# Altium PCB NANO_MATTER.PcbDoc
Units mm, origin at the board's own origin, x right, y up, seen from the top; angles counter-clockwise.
Board outline 43.18 x 17.78 mm, 4 copper layers (TOP, GND, SIG, BOTTOM), stack 1.586 mm thick; 66 components, 64 nets, 297 pads, 160 vias.
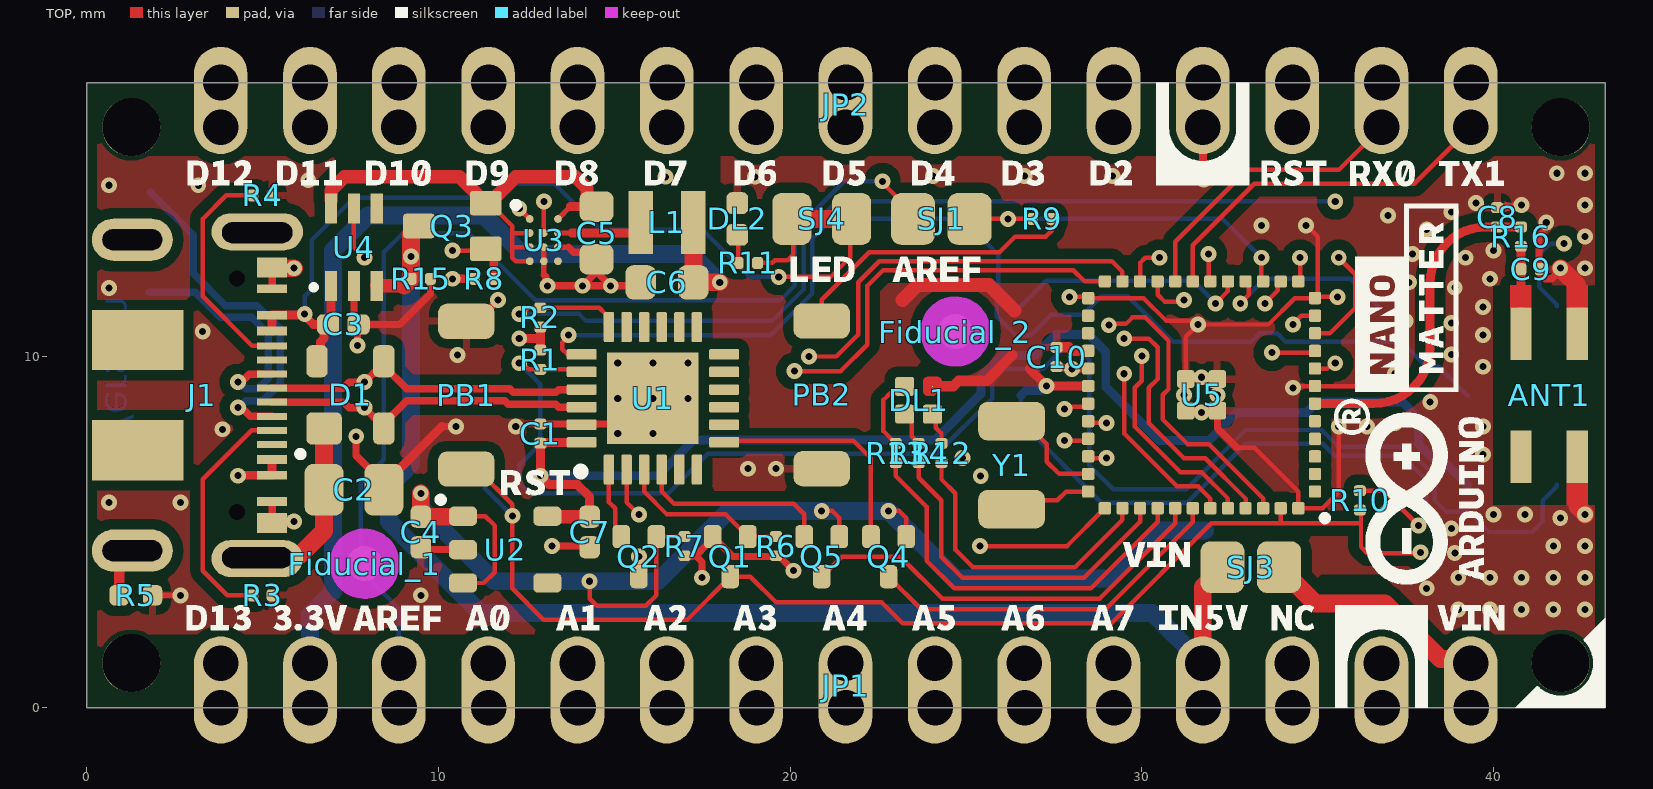
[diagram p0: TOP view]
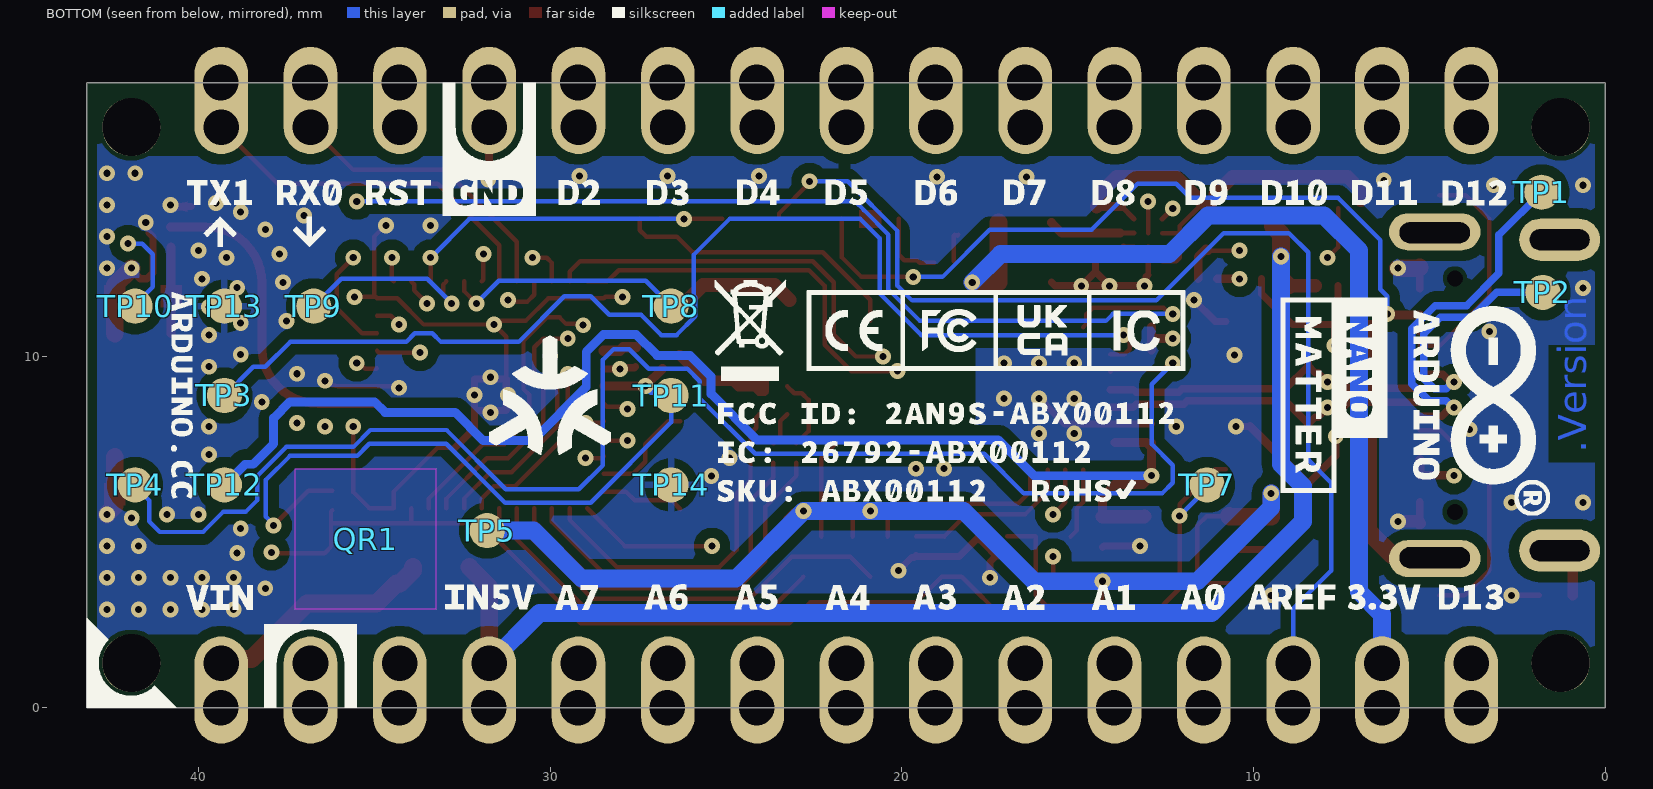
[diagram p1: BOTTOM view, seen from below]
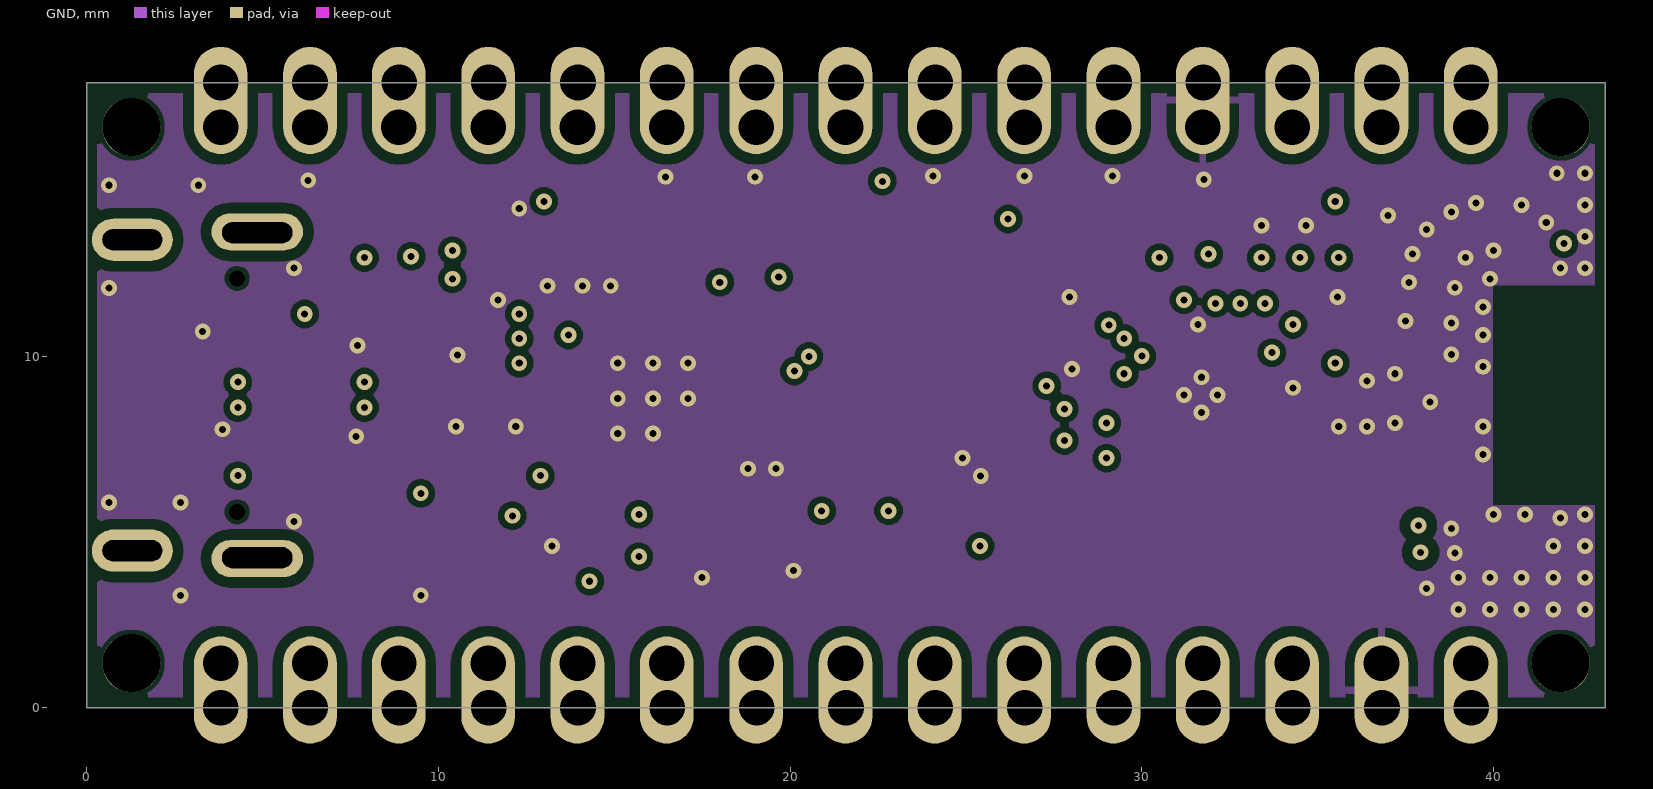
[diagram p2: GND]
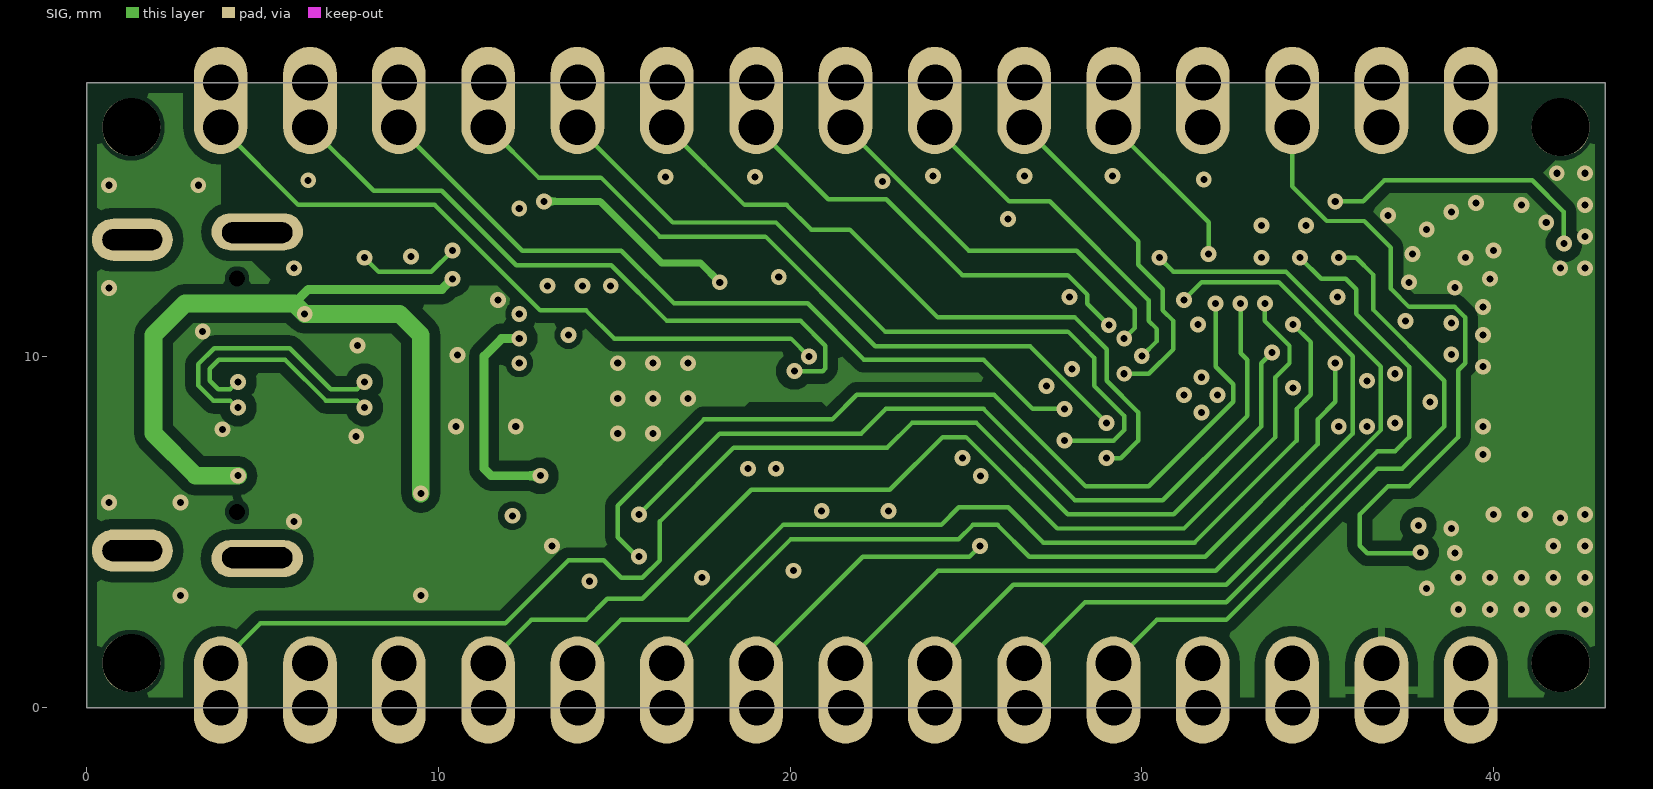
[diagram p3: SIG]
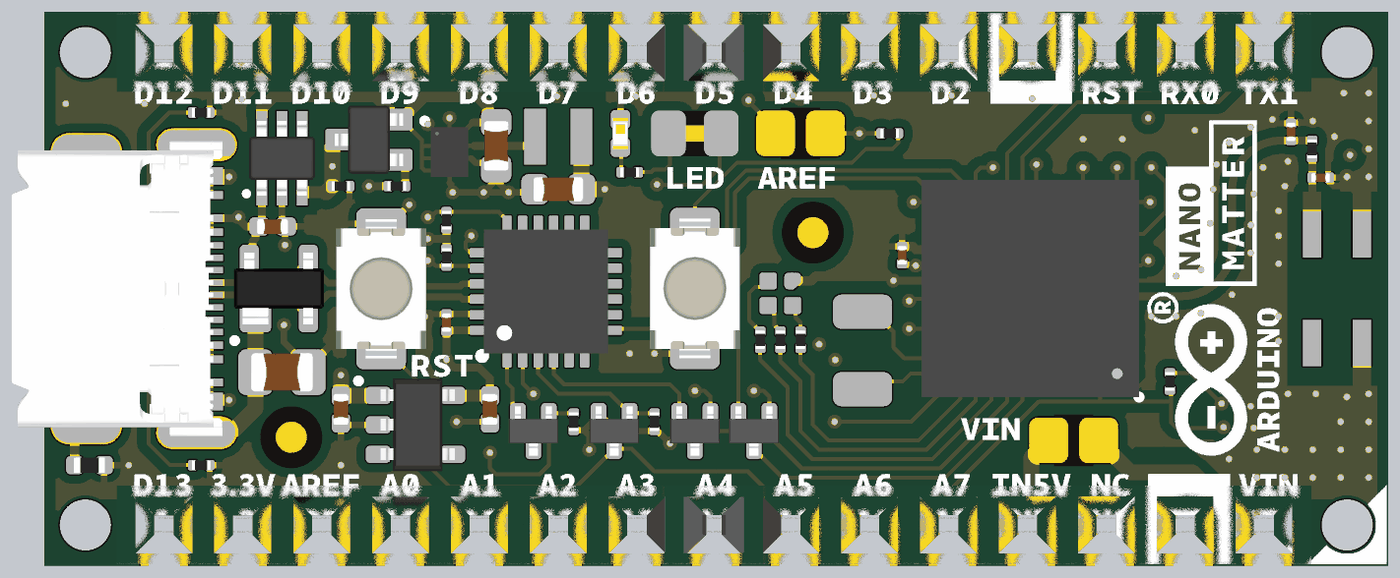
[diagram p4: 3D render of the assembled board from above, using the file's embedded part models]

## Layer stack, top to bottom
Top Solder: solder mask 0.0102, Solder Resist, Dk 3.5
TOP: signal copper 0.018
Dielectric 1: prepreg 0.14, PP-014, Dk 4.2
GND: signal copper 0.035
Dielectric2: core 1.2, FR-4, Dk 4.8
SIG: signal copper 0.035
Dielectric3: prepreg 0.14, PP-014, Dk 4.2
BOTTOM: signal copper 0.018
Bottom Solder: solder mask 0.0102, Solder Resist, Dk 3.5

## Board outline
0,0 0,17.78 43.18,17.78 43.18,0

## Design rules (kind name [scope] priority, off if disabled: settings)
BoardOutlineClearance USBC_outlineclearance [Component = 'J1'] p1: gap=0.1 ignorepadtopadclearanceinfootprint=FALSE
BoardOutlineClearance Castellated [((ObjectKind = 'Pad') And (Component = 'JP1')) OR                                                                                    ((ObjectKind = 'Pad') And (Component = 'JP2'))] p2: gap=0 ignorepadtopadclearanceinfootprint=FALSE
BoardOutlineClearance Silks [(OnLayer('Top Overlay') OR OnLayer('Bottom Overlay'))] p3: gap=0 ignorepadtopadclearanceinfootprint=FALSE
BoardOutlineClearance [All] p4: gap=0.3 ignorepadtopadclearanceinfootprint=FALSE
Clearance SolderJumpers [(ObjectKind = 'Region') And (Net = 'NetR11_2') And (Area = '0.315 sq.') vs (ObjectKind = 'Pad') And (Layer = 'TOP') And (Net = 'VUSB') And (Component = 'SJ4') And (Name = 'SJ4-1')] p1: gap=0 ignorepadtopadclearanceinfootprint=TRUE
Clearance Clearance_Teardrop [IsTeardrop] p2: gap=0.127 ignorepadtopadclearanceinfootprint=TRUE
Clearance COPPER_0.3mm [All] p3: gap=0.127 ignorepadtopadclearanceinfootprint=TRUE except(0.3: Arc-Fill Arc-Poly Arc-Region Track-Fill Track-Poly Track-Region SMDPad-Fill SMDPad-Poly SMDPad-Region THPad-Fill THPad-Poly THPad-Region Via-Fill Via-Poly Via-Region Fill-Fill Fill-Poly Fill-Region Poly-Poly Poly-Region Region-Region)
Clearance "Generic clearance 0.127mm" [All] p4: gap=0.127 ignorepadtopadclearanceinfootprint=TRUE
ComponentClearance [All] p1: gap=0.2 collisioncheckmode=3 verticalgap=0 showdistances=TRUE
DiffPairsRouting USB [InDifferentialPairClass('USB')] p1: maxlimit=0.254 minlimit=0.127 mostfreqgap=0.254 toplayer_maxgap=0.127 toplayer_prefgap=0.127 toplayer_minwidth=0.213 toplayer_maxwidth=0.213 toplayer_prefwidth=0.213 midlayer2_mingap=0.197 midlayer2_maxgap=0.197 midlayer2_prefgap=0.197 midlayer2_minwidth=0.127 midlayer2_maxwidth=0.127 midlayer2_prefwidth=0.127 bottomlayer_maxgap=0.127 bottomlayer_prefgap=0.127 bottomlayer_minwidth=0.213 bottomlayer_maxwidth=0.213 bottomlayer_prefwidth=0.213 impedanceprofiledriven=TRUE impedanceprofileid={E6B00C31-4C8E-439C-824F-D2B2CDC26F9C} impedanceprofilevalue=90.000000 maxuncoupledlength=12.7
Height [All] p1: minheight=0 maxheight=30 prefheight=12.7
HoleSize [All] p1: absolutevalues=TRUE maxlimit=30 minlimit=0.2 maxpercent=80.000 minpercent=20.000
HoleToHoleClearance [All] p1: gap=0.25 allowstackedmicrovias=FALSE
PlaneConnect [All] p1: pad.planeconnectstyle=Relief pad.reliefexpansion=0.508 pad.reliefentries=4 pad.reliefconductorwidth=0.254 pad.reliefairgap=0.254 via.planeconnectstyle=Direct via.reliefexpansion=0.508 via.reliefentries=4 via.reliefconductorwidth=0.254 via.reliefairgap=0.254
PolygonConnect [All] p1: thpad.connectstyle=Relief thpad.reliefconductorwidth=0.2 thpad.reliefentries=4 thpad.polygonreliefangle="90 Angle" thpad.airgapwidth=0.254 smdpad.connectstyle=Relief smdpad.reliefconductorwidth=0.2 smdpad.reliefentries=4 smdpad.polygonreliefangle="90 Angle" smdpad.airgapwidth=0.254 via.connectstyle=Direct via.reliefconductorwidth=0.254 via.reliefentries=4 via.polygonreliefangle="90 Angle" via.airgapwidth=0.254
RoomDefinition TOP [InComponentClass('TOP')] p1: confinementstyle=ConfineIn formatcopy=TRUE lockcomponents=FALSE outline 44.4,1.5 48.8,1.5 48.8,8.5 44.4,8.5
RoutingVias StandardVias [All] p1: holewidth=0.2 width=0.45 viastyle="Through Hole" minholewidth=0.2 minwidth=0.45 maxholewidth=0.2 maxwidth=0.45
SMDToCorner [All] p1: distance=39370
ShortCircuit short_jumper [(ObjectKind = 'Region') And (Net = 'NetR11_2') And (Area = '0.315 sq.') vs (ObjectKind = 'Pad') And (Layer = 'TOP') And (Net = 'VUSB') And (Component = 'SJ4') And (Name = 'SJ4-1')] p1: allowed=TRUE
ShortCircuit [All] p2: allowed=FALSE
SilkToSilkClearance [All] p1: silktosilkclearance=0.2
SilkToSolderMaskClearance [IsPad] p1: minsilkscreentomaskgap=0.1 clearancetoexposedcopper=TRUE
SolderMaskExpansion VIAtented [IsVia] p1: expansion=0.102 istentingtop=TRUE
SolderMaskExpansion [All] p2: expansion=0.05 istentingtop=FALSE
UnConnectedPin [All] p1:
UnRoutedNet [All] p1: checkbadconnections=TRUE
ViasUnderSMD [All] p1: allowed=FALSE
Width [All] p1: maxlimit=0.508 minlimit=0.127 preferedwidth=0.254
Width StandardTraces [InNetClass('ANT')] p2: maxlimit=5 minlimit=0.127 preferedwidth=0.239 toplayer_minwidth=0.239 toplayer_maxwidth=0.239 bottomlayer_minwidth=0.239 bottomlayer_maxwidth=0.239 impedanceprofiledriven=TRUE impedanceprofileid={62AF9E0A-4658-4788-9E1D-AE6CB9A6C4CD} impedanceprofilevalue=50.000000 minimp=50.000000 maximp=50.000000 favimp=50.000000
20 further rules are at their usual default settings.

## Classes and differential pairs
component class TOP: Fiducial_1 Fiducial_2 QR1
net class ANT: NetANT1_1 NetC8_1
component class U_MGM240S: ANT1 C8 C9 C10 R16 TP7 TP8 TP9 TP14 U5 Y1
differential pair class USB: D
component class U_USB: C2 D1 J1 R3 R4 R5 TP1 TP2
component class "U_SAMD11 USB Bridge": C1 Q1 Q2 Q4 Q5 R1 R2 R6 R7 TP3 TP4 TP10 TP13 U1
component class U_POWER: C3 C4 C5 C6 C7 L1 L? Q3 R8 R15 TP5 TP11 TP12 U2 U3 U4
component class U_INTERFACE: DL1 DL2 JP1 JP2 PB1 PB2 R9 R10 R11 R12 R13 R14 SJ1 SJ3 SJ4
differential pair D: +D_P -D_N

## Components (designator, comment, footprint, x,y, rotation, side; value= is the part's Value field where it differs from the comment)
ANT1 "2450AT42E010BE" 2450AT42E0100E 41.58,8.89 r270 top
C1 "CL03A104KP3NNNC" CAP-0201 12.9,7.8 r270 top value=100nF
C2 "FV21X472K102ECG" CAP-0805 7.6,6.2 r180 top value=4.7nF
C3 "CL05A105KP5NNNC" CAP-0402 7.3,10.9 r0 top value=1µF
C4 "CL05A105KP5NNNC" CAP-0402 9.5,5 r90 top value=1µF
C5 "C1608A106M250NT" CAP-0603 14.5,13.5 r270 top value=10µF
C6 "C1608A106M250NT" CAP-0603 16.5,12.1 r0 top value=10µF
C7 "CL05A105KP5NNNC" CAP-0402 14.3,5 r90 top value=1µF
C8 "CAP-0201-DNP" CAP-0201 40.1,13.95 r90 top
C9 "CAP-0201-DNP" CAP-0201 41.055,12.473 r0 top
C10 "CL03A104KP3NNNC" CAP-0201 27.575,9.975 r90 top value=100nF
D1 "PRTR5V0U2X,215" SOT190P230X110-4N 7.5,8.9 r0 top
DL1 "UHD1110-FKA-CL1A13R3Q1BBQFMF3" UHD1110-FKA-CL1A13R3Q1BBQFMF3 23.655,8.745 r270 top
DL2 "KPHHS-1005SURCK" 0402-LED 18.5,13.9 r90 top
Fiducial_1 "Fiducial mark 1mm" "Fiducial mark 1mm-Footprint-1" 7.9,4.1 r90 top
Fiducial_2 "Fiducial mark 1mm" "Fiducial mark 1mm-Footprint-1" 24.7,10.7 r90 top
J1 "CX90B-16P" CX90B-16P-Footprint-1 3.288,8.89 r270 top locked
JP1 "PINHD-1X15-NANO-ANALOG-CASTELLATED" PINHD-1X14_5VF#1 3.81,1.27 r180 top locked
JP2 "PINHD-1X15-NANO-DIGITAL-CASTELLATED" PINHD-1X14_5VF#2 39.37,16.51 r0 top locked
L1 "MAKK2016T3R3M" MAKK2016T3R3M-Footprint-1 16.5,13.8 r0 top value=3.3µH
PB1 "IT-1185AP1C-160G-GTR" C&K_PTS820_NO_HOLES-1 10.794,8.89 r270 top locked
PB2 "IT-1185AP1C-160G-GTR" C&K_PTS820_NO_HOLES-1 20.9,8.9 r90 top
Q1 "2N7002T-7-F" SOT523 18.3,4.3 r180 top
Q2 "2N7002T-7-F" SOT523 15.7,4.3 r180 top
Q3 "DMP2165UW-7" DIOD-SOT323-3_V 10.4,13.7 r180 top
Q4 "2N7002T-7-F" SOT523 22.8,4.3 r180 top
Q5 "2N7002T-7-F" SOT523 20.9,4.3 r180 top
QR1 "QR CODE 4x4mm" "QR CODE 4x4mm" 35.25,4.8 r180 bottom
R1 "RC0201FR-07100KL" RES-0201 12.9,9.9 r90 top value=100k
R2 "RC0201FR-07100KL" RES-0201 12.9,11.1 r90 top value=100k
R3 "RC0201FR-075K1L" RES-0201 5,3.2 r180 top value=5.1k
R4 "RC0201FR-075K1L" RES-0201 5,14.573 r180 top value=5.1k
R5 "CRCW04021M00FKED" RES-0402 1.4,3.2 r180 top value=1M
R6 "RC0201FR-07100KL" RES-0201 19.6,4.6 r270 top value=100k
R7 "RC0201FR-07100KL" RES-0201 17,4.6 r270 top value=100k
R8 "RC0201FR-07100KL" RES-0201 11.3,12.2 r0 top value=100k
R9 "RC0201FR-071KL" RES-0201 27.175,13.9 r180 top value=1k
R10 "RC0201FR-075K1L" RES-0201 36.2,5.9 r90 top value=5.1k
R11 "RC0201FR-071KL" RES-0201 18.8,12.65 r0 top value=1k
R12 "CRCW0201499RFKED" RES-0201 24.305,7.245 r270 top value=499
R13 "CRCW0201499RFKED" RES-0201 23.005,7.245 r270 top value=499
R14 "CRCW0201499RFKED" RES-0201 23.655,7.245 r270 top value=499
R15 "RC0201FR-0710ML" RES-0201 9.5,12.2 r0 top value=10M
R16 "CRCW02010000Z0ED" RES-0201 40.78,13.4 r270 top value=0
SJ1 "SMD solder JUMPER 0805" SJ#1 24.3,13.9 r0 top
SJ3 "SMD solder JUMPER 0805" SJ#1 33.1,4 r180 top
SJ4 "SMD solder JUMPER CLOSED" SJ#2 20.9,13.9 r180 top
TP1 "Test point 1.00mm" TP-1.00MM 1.81,14.66 r90 bottom
TP2 "Test point 1.00mm" TP-1.00MM 1.778,11.811 r90 bottom
TP3 "Test point 1.00mm" TP-1.00MM 39.263,8.881 r90 bottom locked
TP4 "Test point 1.00mm" TP-1.00MM 41.803,6.341 r90 bottom locked
TP5 "Test point 1.00mm" TP-1.00MM 31.795,5.041 r90 bottom locked
TP7 "Test point 1.00mm" TP-1.00MM 11.323,6.341 r90 bottom
TP8 "Test point 1.00mm" TP-1.00MM 26.563,11.421 r90 bottom
TP9 "Test point 1.00mm" TP-1.00MM 36.723,11.421 r90 bottom
TP10 "Test point 1.00mm" TP-1.00MM 41.803,11.421 r90 bottom locked
TP11 "Test point 1.00mm" TP-1.00MM 26.563,8.881 r90 bottom
TP12 "Test point 1.00mm" TP-1.00MM 39.263,6.341 r90 bottom locked
TP13 "Test point 1.00mm" TP-1.00MM 39.263,11.421 r90 bottom locked
TP14 "Test point 1.00mm" TP-1.00MM 26.563,6.341 r90 bottom
U1 "ATSAM-D11-D14A-MUT" VQFN24 16.1,8.8 r180 top
U2 "AP2112K-3.3TRG1" SOT25 11.9,4.5 r270 top
U3 "MP28210GC–Z" MP28210 13,13.3 r270 top
U4 "LM66100DCKR" SOT65P210X110-6N 7.6,13.1 r90 top
U5 "MGM240SD22VNA2R" MGM240SD22VNA 31.7,8.9 r180 top locked
Y1 "CM315D32768DZFT" ABS07 26.3,6.9 r90 top

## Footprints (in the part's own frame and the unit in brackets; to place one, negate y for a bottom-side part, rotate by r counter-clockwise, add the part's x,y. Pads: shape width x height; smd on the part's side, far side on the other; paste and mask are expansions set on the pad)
0402-LED [mm]
  rrect50% 0.62x0.62 smd mask+0.05: A(-0.45,0) C(0.45,0)
  body extent -0.5,-0.25 0.5,0.25, height 0.5
2450AT42E0100E [mm]
  rect 1.5x0.6 smd: 1(-1.75,-0.8) 2(1.75,-0.8) 3(1.75,0.8) 4(-1.75,0.8)
  TOP region: -2.5,0.5 -3.13,0.5 -3.13,1.1 -2.5,1.1
  TOP region: -2.5,-1.1 -3.13,-1.1 -3.13,-0.5 -2.5,-0.5
  TOP region: 2.5,0.5 3.13,0.5 3.13,1.1 2.5,1.1
  body extent -2.5,-1 2.5,1, height 1.7
ABS07 [mm]
  rrect50% 1.1x1.9 smd: 1(-1.25,0) 2(1.25,0)
  body extent -1.65,-0.83 1.65,0.83, height 0.9
C&K_PTS820_NO_HOLES-1 [mm]
  rrect49% 1x1.6 smd mask+0.05: 1(-2.1,0) 2(2.1,0)
  body extent -2.25,-1.45 2.25,1.45, height 2
CAP-0201 [mm] "Chip Capacitor, 2-Leads, Body 0201 (in) 0603 (mm) IPC Medium Density"
  rrect52% 0.31x0.34 smd mask+0.05: 1(-0.275,0) 2(0.275,0)
  body extent -0.3,-0.15 0.3,0.15, height 0.3
CAP-0402 [mm] "Chip Capacitor, 2-Leads, Body  0402 (in) 1005 (mm), IPC Medium Density"
  rrect52% 0.63x0.58 smd mask+0.05: 1(-0.435,0) 2(0.435,0)
  body extent -0.5,-0.25 0.5,0.25, height 0.5
CAP-0603 [mm] "Chip Capacitor, Body 0603 imperial,1.6x0.8mm, IPC High Density"
  rrect51% 0.87x0.97 smd mask+0.05: 1(-0.75,0) 2(0.75,0)
  body extent -0.8,-0.4 0.8,0.4, height 0.8
CAP-0805 [mm] "Chip Capacitor, Body 0805 imperial, 2.0x1.2mm, IPC Medium Density"
  rrect45% 1.11x1.47 smd mask+0.05: 1(-0.85,0) 2(0.85,0)
  body extent -1,-0.62 1,0.63, height 1.25
CX90B-16P-Footprint-1 [mm]
  rect 0.57x0.85 smd mask+0.05: A1(-3.635,1.988) A12(3.635,1.988)
  rect 0.25x0.85 smd mask+0.05: A4(-2.275,1.988) A9(2.275,1.988) B1(3.025,1.988) B4(1.825,1.988) B9(-1.825,1.988) B12(-3.025,1.988)
  rect 0.2x0.85 smd mask+0.05: A5(-1.4,1.988) A6(-0.6,1.988) A7(0.6,1.988) A8(1.4,1.988) B5(1,1.988) B6(0.2,1.988) B7(-0.2,1.988) B8(-1,1.988)
  round 0.2 hole 0.45 unplated paste-2539.97 mask+0.2: FIXING(-3.32,0.988) FIXING(3.32,0.988)
  rect 1.71x2.6 smd paste-0.3 mask+0.05: FIXING(-1.565,-1.837) FIXING(1.565,-1.837)
  oval 1.05x2.6 hole 0.6 slot 2 at 90 deg copper offset -0.025,0 mask+0.05: SHIELD1(-4.62,1.563)
  oval 1.05x2.6 hole 0.6 slot 2 at 90 deg copper offset 0.025,0 mask+0.05: SHIELD2(4.62,1.563)
  oval 1.2x2.3 hole 0.6 slot 1.7 at 90 deg mask+0.05: SHIELD3(-4.42,-1.987) SHIELD4(4.42,-1.987)
  body extent -4.77,-4.4 4.77,2.4, height 3.17
DIOD-SOT323-3_V [mm] "SOT323, 3-Leads, Body 2.2x1.35mm, Pitch 0.65mm"
  rrect25% 0.9x0.7 smd mask+0.05: 1(-0.95,0.65) 2(-0.95,-0.65) 3(0.95,0)
  body extent -1.1,-1.1 1.1,1.1, height 1.07
"Fiducial mark 1mm-Footprint-1" [mm]
  round 1 smd paste-10 mask+0.5: 1(0,0)
  TOP keep-out circle w1: c0,0 r0.5
MAKK2016T3R3M-Footprint-1 [mm]
  rect 0.7x1.8 smd mask+0.05: 1(-0.75,0) 2(0.75,0)
  body extent -1,-0.8 1,0.8, height 1
MGM240SD22VNA [mm]
  rrect30% 0.35x0.35 smd mask+0.05: 1(-3.225,2.75) 2(-3.225,2.25) 3(-3.225,1.75) 4(-3.225,1.25) 5(-3.225,0.75) 6(-3.225,0.25) 7(-3.225,-0.25) 8(-3.225,-0.75) 9(-3.225,-1.25) 10(-3.225,-1.75) 11(-3.225,-2.25) 12(-3.225,-2.75) 13(-2.75,-3.225) 14(-2.25,-3.225) 15(-1.75,-3.225) 16(-1.25,-3.225) 17(-0.75,-3.225) 18(-0.25,-3.225) 19(0.25,-3.225) 20(0.75,-3.225) 21(1.25,-3.225) 22(1.75,-3.225) 23(2.25,-3.225) 24(2.75,-3.225) 25(3.225,-2.75) 26(3.225,-2.25) 27(3.225,-1.75) 28(3.225,-1.25) 29(3.225,-0.75) 30(3.225,-0.25) 31(3.225,0.25) 32(3.225,0.75) 33(3.225,1.25) 34(3.225,1.75) 35(3.225,2.25) 36(3.225,2.75) 37(2.75,3.225) 38(2.25,3.225) 39(1.75,3.225) 40(1.25,3.225) 41(0.75,3.225) 42(0.25,3.225) 43(-0.25,3.225) 44(-0.75,3.225) 45(-1.25,3.225) 46(-1.75,3.225) 47(-2.25,3.225) 48(-2.75,3.225)
  rrect30% 0.5x0.5 smd mask+0.05: 49(-0.45,0.45) 50(0.45,0.45) 51(0.45,-0.45) 52(-0.45,-0.45)
  silkscreen extent -3.55,3.46 -3.46,3.55, body extent -3.5,-3.5 3.5,3.5, height 1.27
MP28210 [mm]
  round 0.22 smd paste+0 mask+0.05: A1(-0.6,-0.4) A3(-0.6,0.4) B1(-0.2,-0.4) B2(-0.2,0) B3(-0.2,0.4) C1(0.2,-0.4) C2(0.2,0) C3(0.2,0.4) D1(0.6,-0.4) D2(0.6,0) D3(0.6,0.4)
  silkscreen extent -1.05,-0.85 -0.95,-0.75, body extent -0.8,-0.6 0.8,0.6, height 0.58
PINHD-1X14_5VF#1 [mil]
  oval 60x120 hole 40 copper offset 0,30 paste-99999: 1(0,0) 2(-100,0) 3(-199.41,0) 4(-299.41,0) 5(-399.41,0) 6(-499.41,0) 7(-599.41,0) 8(-699.41,0) 9(-799.41,0) 10(-899.41,0) 11(-999.41,0) 12(-1099.41,0) 13(-1199.41,0) 14(-1299.41,0) 15(-1399.41,0)
  round 27.56 hole 40 mask+7.87: 1(0,50) 2(-100,50) 3(-200,50) 4(-300,50) 5(-400,50) 6(-500,50) 7(-600,50) 8(-700,50) 9(-800,50) 10(-900,50) 11(-1000,50) 12(-1100,50) 13(-1200,50) 14(-1300,50) 15(-1400,50)
  body extent -1454,-50 60,50, height 335
PINHD-1X14_5VF#2 [mil]
  oval 60x120 hole 40 copper offset 0,30 paste-99999: 1(-0.59,0) 2(-100.59,0) 3(-200.59,0) 4(-300.59,0) 5(-400.59,0) 6(-500.59,0) 7(-600.59,0) 8(-700.59,0) 9(-800.59,0) 10(-900.59,0) 11(-1000.59,0) 12(-1100.59,0) 13(-1200.59,0) 14(-1300,0) 15(-1400,0)
  round 27.56 hole 40 mask+7.87: 1(0,50) 2(-100,50) 3(-200,50) 4(-300,50) 5(-400,50) 6(-500,50) 7(-600,50) 8(-700,50) 9(-800,50) 10(-900,50) 11(-1000,50) 12(-1100,50) 13(-1200,50) 14(-1300,50) 15(-1400,50)
  body extent -1460,-50 54,50, height 335
"QR CODE 4x4mm" [mm]
  TOP keep-out region: -2,2 2,2 2,-2 -2,-2
RES-0201 [mm] "Chip Resistor, 2-Leads, Body 0201 (in) 0603 (mm) IPC Medium Density"
  rrect52% 0.31x0.34 smd mask+0.05: 1(-0.275,0) 2(0.275,0)
  body extent -0.3,-0.15 0.3,0.15, height 0.24
RES-0402 [mm] "Chip Resistor, 2-Leads, Body  0402 (in) 1005 (mm), IPC Medium Density"
  rrect51% 0.55x0.58 smd mask+0.05: 1(-0.475,0) 2(0.475,0)
  body extent -0.5,-0.25 0.5,0.25, height 0.34
SJ#1 [mm]
  rrect45% 1.25x1.47 smd paste-0.635: 1(-0.805,0) 2(0.805,0)
SJ#2 [mm]
  rrect45% 1.11x1.47 smd mask+0: 1(-0.85,0) 2(0.85,0)
  TOP region: -0.31,0.254 -0.31,-0.254 0.31,-0.254 0.31,0.254
SOT25 [mil]
  rrect50% 21.65x31.5 smd mask+1.97: 1(-37.4,-47.24) 2(0,-47.24) 3(37.4,-47.24) 4(37.4,47.24) 5(-37.4,47.24)
  silkscreen extent -58,-74 -54,-70, body extent -59,-44 59,50, height 43
SOT65P210X110-6N [mm] "SOT23, 6-Leads, Body 1,99x2,10mm, Pitch 0,65mm, IPC Medium Density"
  rect 0.85x0.35 smd mask+0.05: 1(-1.1,0.65) 2(-1.1,0) 3(-1.1,-0.65) 4(1.1,-0.65) 5(1.1,0) 6(1.1,0.65)
  silkscreen extent -1.19,1.09 -1.09,1.19, body extent -1.2,-1.06 1.2,1.06, height 1.12
SOT190P230X110-4N [mm]
  rrect33% 1.01x0.91 smd paste+0 mask+0.05: 1(-0.75,-0.955)
  rrect49% 0.61x0.91 smd paste+0 mask+0.05: 2(0.95,-0.955) 3(0.95,0.955) 4(-0.95,0.955)
  silkscreen extent -1.47,-1.73 -1.37,-1.63, body extent -1.45,-1.15 1.45,1.15, height 1
SOT523 [mm]
  rrect50% 0.5x0.66 smd: D(0,0.57) G(-0.5,-0.57) S(0.5,-0.57)
  body extent -0.8,-0.8 0.8,0.8, height 0.8
TP-1.00MM [mm]
  rrect100% 1x1 smd paste-2.54: X(0,0)
UHD1110-FKA-CL1A13R3Q1BBQFMF3 [mm]
  rrect25% 0.54x0.54 smd mask+0.05: 1(-0.395,-0.395) 2(0.395,-0.395) 3(0.395,0.395)
  round 0.025 smd mask+0.05: 4(-0.395,0.395)
  TOP region: -0.35,0.665 -0.125,0.44 -0.125,0.265 -0.136,0.212 -0.166,0.166 -0.212,0.136 -0.265,0.125 -0.265,0.125 -0.525,0.125 -0.578,0.136 -0.624,0.166 -0.654,0.212 -0.665,0.265 -0.665,0.265 -0.665,0.525 -0.654,0.578 -0.624,0.624 -0.578,0.654 -0.525,0.665 -0.525,0.665
  body extent -0.5,-0.5 0.5,0.5, height 0.63
VQFN24 [mm]
  rrect25% 0.3x0.85 smd mask+0.05: 1(1.25,2.025) 2(0.75,2.025) 3(0.25,2.025) 4(-0.25,2.025) 5(-0.75,2.025) 6(-1.25,2.025) 13(-1.25,-2.025) 14(-0.75,-2.025) 15(-0.25,-2.025) 16(0.25,-2.025) 17(0.75,-2.025) 18(1.25,-2.025)
  rrect25% 0.85x0.3 smd mask+0.05: 7(-2.025,1.25) 8(-2.025,0.75) 9(-2.025,0.25) 10(-2.025,-0.25) 11(-2.025,-0.75) 12(-2.025,-1.25) 19(2.025,-1.25) 20(2.025,-0.75) 21(2.025,-0.25) 22(2.025,0.25) 23(2.025,0.75) 24(2.025,1.25)
  rect 2.6x2.6 smd paste-5 mask+0.05: EXP(0,0)
  silkscreen extent 1.95,1.98 2.15,2.18, body extent -2,-2 2,2, height 0.9

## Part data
ANT1: library part Y0004-A.2, "ANTENNA CHIP 2.4GHZ", Frequency=2.4GHz, Manufacturer=Johanson, Max Frequency=2.48GHz, Max Power Dissipation=2W
C1 C10: library part C0113-A.6, "CAP CHIP 0201 100nF 10% 10V X5R", Case Code (Imperial)=0201, Dielectric=X5R, Manufacturer="Samsung Electro-Mechanics", Tolerance=10%, Voltage=10V
C2: library part C0059-A.14, "CAP CHIP 0805 4.7nF 10% 1000V X7R", Case Code (Imperial)=0805, Dielectric=X7R, Manufacturer="PSA Shenzen", Manufacturer 2=KEMET, Part number 2=C0805V472KDRACTU, Part number 3=C0805C472KDRACTU, Tolerance=10%, Voltage=1kV
C3 C4 C7: library part C0017-A.14, "CAP CHIP 0402 1uF 10% 10V X5R", Case Code (Imperial)=0402, Dielectric=X5R, Manufacturer="Samsung Electro-Mechanics", Manufacturer 2="Murata Electronics", Part number 2=GCM155C71A105KE38D, Tolerance=10%, Voltage=10V
C5 C6: library part C0047-A.18, "CAP CHIP 0603 10uF 20% 25V X5R", Case Code (Imperial)=0603, Dielectric=X5R, Manufacturer=Hottech, Manufacturer 2="Murata Electronics", Part number 2=CL10A106MA8NRNC, Tolerance=20%, Voltage=25V
C8 C9: library part UT0015-A.7, "DNP CAP CHIP 0201"
D1: library part D0025-A.5, "TVS ARRAY 4LIN.8kV 1pF SOT143B", Manufacturer=Nexperia
DL1: library part L0026-A.4, "LED RGB BLACK BODY SMD", Manufacturer="Cree LED"
DL2: library part L0004-A.7, "LED SMD 0402 RED630 220mcd 120^", Manufacturer=Kingbright
Fiducial_1 Fiducial_2: library part UT0023-A.7, "Fiducial mark 1mm clearance 2mm"
J1: library part J0272-A.3, "CONN RCPT USB3.1 TYPEC 16POS SMD", Manufacturer=Hirose
JP1: library part J0158-A.4, "CONN THD SOCKET F/1/D 15V JANALOG NANO-TYPE CASTELLATED"
JP2: library part J0183-A.4, "CONN THD SOCKET F/1/D 15V JDIGITAL NANO-TYPE CASTELLATED"
L1: library part I0045-A.10, "IND CHIP 0806 3.3 uH 20% 1.2A", Case Code (Imperial)=0806, Case Code (Metric)=2016, Current Rating=1.2A, DC Resistance (DCR)=255mR, Inductance=3.3µH, Manufacturer="Taiyo Yuden", Manufacturer 2=Murata, Manufacturer Part Number 2=LQM2MPN3R3NG0L, Max DC Current=1.15A, Max Operating Temperature=105°C, Min Operating Temperature=-40°C, Package Quantity=3000, Resistor Type=Wirewound, Test Frequency=2MHz, Tolerance=20%
PB1 PB2: library part B0001-A.7, "PUSHBUTTON WHITE NO ANCHORS", Color=White, Manufacturer=Switronic
Q1 Q2 Q4 Q5: library part T0003-A.2, "MOSFET N-CH 60V 115mA SOT523", Manufacturer="Diodes Inc."
Q3: library part T0050-2, "MOSFET P-CH Vds -20V, Id 2A, VGSS+-12V, SOT323", Manufacturer="Diodes Incorporated"
QR1: library part QR-0001-A.2, "QR CODE 4x4mm on layer 34 (This is not a component)", Manufacturer="This is not a component"
R1 R2 R6 R7 R8: library part R0146-A.21, "RES CHIP 0201 100k 1% 1/20W", Case Code (Imperial)=0201, Manufacturer=Yageo, Manufacturer 2="Samsung Electro-Mechanics", Power=50mW, Temperature Coefficient=200ppm, Tolerance=1%
R3 R4 R10: library part R0169-A.24, "RES CHIP 0201 5.1k 1% 1/20W", Case Code (Imperial)=0201, Manufacturer=Yageo, Power=50mW, Temperature Coefficient=200ppm, Tolerance=1%
R5: library part R0058-A.24, "RES CHIP 0402 1M 1% 1/16W", Case Code (Imperial)=0402, Manufacturer=Vishay, Power=62.5mW, Temperature Coefficient=100ppm, Tolerance=1%
R9 R11: library part R0195-A.22, "RES CHIP 0201 1k 1% 1/20W", Case Code (Imperial)=0201, Manufacturer=Yageo, Power=50mW, Temperature Coefficient=200ppm, Tolerance=1%
R12 R13 R14: library part R0185-A.22, "RES CHIP 0201 499R 1% 1/20W", Case Code (Imperial)=0201, Manufacturer=Vishay, Power=50mW, Temperature Coefficient=100ppm, Tolerance=1%
R15: library part R0297-A.1, "RES CHIP 0201 10M 1% 1/20W", Case Code (Imperial)=0201, Manufacturer=YAGEO, Power=50mW, Temperature Coefficient=200ppm, Tolerance=1%
R16: library part R0140-A.21, "RES CHIP 0201 0R", Case Code (Imperial)=0201, Manufacturer=Vishay, Power=50mW, Temperature Coefficient=0ppm, Tolerance=0%
SJ1 SJ3: library part UT0002-A.5, "Solder Jumper 0805 THIS IS NOT A COMPONENT"
SJ4: library part UT0006-A.14, "Solder Jumper shorted pads. This is not a component"
TP1 TP2 TP3 TP4 TP5 TP7 TP8 TP9 TP10 TP11 TP12 TP13 TP14: library part UT0013-A.6, Manufacturer="This is not a component"
U1: library part U0040-A.8, "IC uC Cortex M0, 16KB flash, 4KB SRAM, 48MHz, USB, 3x SERCOM, RTC, 12PWM, ADC 12b, DAC 10b, VDD 1.6V to 3.6V, QFN24 4x4mm", Manufacturer=Microchip
U2: library part U0027-A.11, "IC LDO Vin max 6.5V Vout 3V3 Iout 600mA +EN  SOT25", Manufacturer="Diodes Inc"
U3: library part U0073-A.4, "IC BUCK Vin 2-5.5V, Iout 1A, Fsw 1.5MHz, Duty 100%, Iq 500nA, CSP12 1.2x1.6mm", Manufacturer=MPS
U4: library part U0164-A.5, "IC IDEAL DIODE 5.5V 1.5A WITH INPUT POLARITY PROTECTION", Manufacturer="Texas Instruments"
U5: library part U0354-A.5, "802.15.4, Bluetooth Bluetooth v5.3, Thread, Zigbee® Transceiver Module 2.4GHz PCB Trace, Antenna Not Included, U.FL Surface Mount", Manufacturer="Silicon Labs"
Y1: library part X0003-A.5, "CRYSTAL 32.768kHz 20ppm 12.5pF SMD 1.6x0.9mm", Frequency=32.768kHz, Frequency Stability=0.12%, Frequency Tolerance=20ppm, Load Capacitance=12.5pF, Manufacturer="Citizen FineDevice", Max Operating Temperature=85°C, Min Operating Temperature=-40°C, Series Resistance=70kR

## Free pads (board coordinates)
  round 1.651 hole 1.651 unplated: MH(1.27,1.27) MH(1.27,16.51) MH(41.91,1.27) MH(41.91,16.51)

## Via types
v1: diameter 0.45, hole 0.2, TOP to BOTTOM, tented both sides, 160 vias

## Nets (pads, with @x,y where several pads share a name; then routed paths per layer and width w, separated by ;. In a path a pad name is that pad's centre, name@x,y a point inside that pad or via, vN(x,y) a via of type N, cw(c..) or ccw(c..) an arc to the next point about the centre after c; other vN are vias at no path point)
+3V3: C6.2 C10.2 DL1.4 JP1.2 L1.2 R10.2 TP11.X U3.B2 U5.28 U5.30 | length 61.3
  TOP w0.127: U3.B2 v1(13,14.4) ; R10.2 36.878,6.175 v1(37.863,5.189)
  TOP w0.254: 26.805,9.643 v1(27.294,9.154) 27.988,9.154 27.992,9.15 U5.30
  TOP w0.3: DL1.4 24.64,9.14 24.8,9.3 25.6,9.3 26.321,10.021 ; C10.2 27.927,10.25 28.027,10.15 U5.28
  TOP w0.4: 23.2,11.6 23.627,12.027 25.654,12.027 26.381,11.3
  TOP w0.508: L1.2 C6.2 v1(18,12.1)
  SIG w0.203: v1(13,14.4) 14.6,14.4 16.35,12.65 17.45,12.65 v1(18,12.1)
  BOTTOM w0.127: TP11.X 26.563,8.119 28.849,5.833 31.284,5.833 32.957,7.506 35.147,7.506 35.49,7.164 37.401,7.164 38.081,6.483 38.081,5.431 37.863,5.213 v1(37.863,5.189)
  BOTTOM w0.254: TP11.X 26.706,9.024 27.125,9.024 27.255,9.154 v1(27.294,9.154)
  BOTTOM w0.508: JP1.2@6.35,1.27 6.35,2.65 7,3.3 7,13 8,14 11.298,14 12.398,12.9 17.2,12.9 v1(18,12.1)
+3V3_D11: C1.2 C7.2 R1.2 R2.1 TP12.X U1.24 U2.5 | length 44.7
  TOP w0.254: v1(12.3,10.5) 12.9,10.5 ; C1.2 v1(12.9,6.6) 13.15,6.35 13.95,6.35 14.3,6 C7.2 ; R1.2 12.9,10.5 ; R2.1 12.9,10.5 ; C1.2@12.953,7.453 13.05,7.55 U1.24@13.945,7.55
  TOP w0.381: U2.5 13.115,5.435 C7.2
  SIG w0.254: v1(12.3,10.5) 11.8,10.5 11.3,10 11.3,6.8 11.5,6.6 v1@12.881,6.6
  BOTTOM w0.254: v1(12.9,6.6) 16.242,6.6 17.263,7.621 24.121,7.621 25.427,8.927 25.427,9.42 26.028,10.021 26.963,10.021 27.563,10.621 28.479,10.621 28.976,10.124 28.976,9.124 30.5,7.6 31.9,7.6 32.7,8.4 34.696,8.4 34.996,8.7 37.4,8.7 37.863,8.237 37.863,7.509 38.445,6.927 38.677,6.927 TP12.X
+5V: JP1.12 Q3.3 R15.1 SJ3.2 U4.3 | length 38.4
  TOP w0.381: U4.3 9.025,12
  TOP w0.508: 9.025,12 R15.1 v1(9.225,12.838) 9.225,13.475 Q3.3 ; JP1.12@31.735,1.27 31.735,3.44 SJ3.2
  SIG w0.508: JP1.12@31.735,1.27 JP1.12@31.97,1.27
  BOTTOM w0.508: v1(9.225,12.838) 9.225,6.925 8.6,6.3 8.6,5.3 11.2,2.7 30.305,2.7 JP1.12@31.735,1.27
A0: JP1.4 U5.14 | length 32.3
  TOP w0.127: v1(33.5,11.5) 33.87,11.87 33.87,12.045 U5.14
  SIG w0.127: JP1.4@11.415,1.27 12.645,2.5 14.2,2.5 14.8,3.1 15.8,3.1 18.9,6.2 22.837,6.2 24.337,7.7 25,7.7 27.6,5.1 31.2,5.1 33.8,7.7 33.8,9.4 34.2,9.8 34.2,10.3 33.5,11 v1(33.5,11.5)
A1: JP1.5 U5.11 | length 28.3
  TOP w0.127: v1@34.3,11 34.387,11 34.537,11.15 U5.11
  SIG w0.127: JP1.5@13.955,1.27 15.185,2.5 17.1,2.5 19.8,5.2 24.3,5.2 24.8,5.7 26.2,5.7 27.2,4.7 31.5,4.7 34.4,7.6 34.4,8.5 34.8,8.9 34.8,10.4 v1(34.3,10.9)
A2: JP1.6 U5.8 | length 25.2
  TOP w0.127: U5.8 34.937,9.638 35.264,9.638 35.427,9.8 v1(35.5,9.8) ; v1@35.55,9.85 v1@35.6,9.9
  SIG w0.127: JP1.6@16.495,1.27 20.025,4.8 24.8,4.8 25.2,5.2 25.9,5.2 26.8,4.3 31.8,4.3 35,7.5 35,8.2 35.5,8.7 v1(35.5,9.8) v1@35.5,9.9 ; v1@35.55,9.85 v1@35.6,9.9
A3: JP1.7 U5.37 | length 11.7
  TOP w0.127: v1(25.4,4.6) 27.875,4.6 U5.37
  SIG w0.127: JP1.7@19.035,1.27 22.065,4.3 25.1,4.3 v1(25.4,4.6)
A4: JP1.8 U5.21 | length 26.4
  TOP w0.127: U5.21 30.45,11.75 30.648,11.552 v1@31.148,11.552 ; v1@31.148,11.652 v1(31.2,11.6)
  SIG w0.127: JP1.8@21.575,1.27 24.205,3.9 32.1,3.9 36,7.8 36,10 33.9,12.1 31.7,12.1 v1(31.2,11.6)
A5: JP1.9 U5.22 | length 26
  TOP w0.127: U5.22 29.95,12.65 30.1,12.8 v1(30.5,12.8)
  SIG w0.127: JP1.9@24.115,1.27 26.345,3.5 32.4,3.5 36.8,7.9 36.8,9.7 34.1,12.4 30.9,12.4 v1(30.5,12.8)
A6: JP1.10 U5.13 | length 21
  TOP w0.127: U5.13 34.5,12.175 v1@34.5,12.7
  SIG w0.127: JP1.10@26.655,1.27 28.385,3 32.4,3 36.7,7.3 37.2,7.3 37.6,7.7 37.6,9.7 36.1,11.2 36.1,11.9 35.8,12.2 35.1,12.2 v1(34.5,12.8)
A7: JP1.11 U5.10 | length 21.6
  TOP w0.127: U5.10 35.35,10.65 36.068,11.368 36.068,12.332 v1(35.6,12.8)
  SIG w0.127: JP1.11@29.195,1.27 30.425,2.5 32.4,2.5 36.7,6.8 37.4,6.8 38.6,8 38.6,9.3 36.576,11.324 36.576,12.319 36.095,12.8 v1(35.6,12.8)
AREF_5: JP1.3 SJ1.1 | length 31.3
  TOP w0.127: v1(22.625,14.972) 22.625,14.926 23.495,14.056 SJ1.1
  BOTTOM w0.127: JP1.3@8.875,1.27 8.875,2.825 7.795,3.905 7.795,6.395 8.451,7.051 8.451,12.951 9,13.5 10.85,13.5 12.766,11.585 19.713,11.585 20.128,12 20.128,13.561 21.539,14.972 v1(22.625,14.972)
CC1_3: J1.A5 R4.2 | length 6.5
  TOP w0.127: R4.2 3.973,14.573 3.3,13.9 3.3,11.7 4.71,10.29 J1.A5
CC2_3: J1.B5 R3.2 | length 6.9
  TOP w0.127: R3.2 4,3.2 3.3,3.9 3.3,6.5 4.69,7.89 J1.B5
CLK: JP1.1 U5.9 | length 39.1
  TOP w0.127: v1(33.7,10.1) 34.875,10.1 U5.9
  SIG w0.127: JP1.1@3.81,1.27 4.94,2.4 11.9,2.4 13.7,4.2 14.7,4.2 15.2,3.7 15.8,3.7 16.3,4.2 16.3,5.3 18.4,7.4 22.767,7.4 23.467,8.1 25.3,8.1 27.895,5.505 30.905,5.505 33.4,8 33.4,9.8 v1(33.7,10.1)
D2_SWV: JP2.5 U5.18 | length 5.5
  TOP w0.127: v1(31.9,12.9) 31.9,12.175 U5.18
  SIG w0.127: JP2.5@29.195,16.51 31.9,13.805 v1(31.9,12.9)
D3: JP2.6 U5.43 | length 14.8
  TOP w0.127: v1(29.5,9.5) 29.5,7.8 31,6.3 31.6,6.3 31.95,5.95 U5.43
  SIG w0.127: JP2.6@26.655,16.51 29.9,13.265 29.9,12.6 30.6,11.9 30.6,11.3 30.9,11 30.9,10.2 30.2,9.5 v1@29.6,9.5
D4: JP2.7 U5.44 | length 15.8
  TOP w0.127: v1(30,10) 30,9.3 29.8,9.1 29.8,8 31.1,6.7 31.7,6.7 32.45,5.95 U5.44
  SIG w0.127: JP2.7@24.115,16.51 26.225,14.4 27.383,14.4 30.2,11.583 30.2,11 30.43,10.77 30.43,10.43 v1(30,10)
D5: JP2.8 U5.45 | length 18.5
  TOP w0.127: v1@29.6,10.5 30.2,10.5 30.45,10.25 30.45,9.35 30.2,9.1 30.2,8.1 31.2,7.1 31.8,7.1 32.95,5.95 U5.45
  SIG w0.127: JP2.8@21.575,16.51 25.085,13 28.148,13 29.8,11.348 29.8,10.8 v1(29.5,10.5)
D6: JP2.9 U5.46 | length 20.9
  TOP w0.127: v1(29.062,10.881) 29.097,10.916 29.55,10.916 29.734,11.1 30.1,11.1 30.759,10.441 30.759,9.059 30.6,8.9 30.6,8.2 31.3,7.5 31.9,7.5 33.45,5.95 U5.46
  SIG w0.127: JP2.9@19.035,16.51 21.083,14.462 22.738,14.462 24.9,12.3 27.9,12.3 28.45,11.75 28.45,11.492 v1(29.062,10.881)
D7: JP2.10 U5.34 | length 19.6
  TOP w0.127: U5.34 28.525,7.1 v1(29,7.1)
  SIG w0.127: JP2.10@16.495,16.51 18.705,14.3 19.9,14.3 20.6,13.6 21.7,13.6 24.2,11.1 28.1,11.1 29,10.2 29,9.3 29.9,8.4 29.9,7.6 29.4,7.1 v1@29.1,7.1
D8: JP2.11 U5.33 | length 22.1
  TOP w0.127: v1@27.9,7.6 28.425,7.6 U5.33
  SIG w0.127: JP2.11@13.955,16.51 16.665,13.8 19.6,13.8 22.7,10.7 27.9,10.7 28.642,9.958 28.642,9.158 29.5,8.3 29.5,7.9 29.2,7.6 v1@27.9,7.6
  other v1: 27.8,7.6
D_N: D1.3 J1.A7 J1.B7 TP1.X U1.21 | length 27
  TOP w0.213: v1@4.35,8.587 4.647,8.29 J1.A7 ; J1.B7 7.29,9.09 7.464,9.264 v1(7.9,9.264) 8.169,9.533 8.255,9.533 8.45,9.728 D1.3 ; D1.3@8.45,9.72 9.1,9.07 12.03,9.07 12.13,8.97 13.339,8.97 13.419,9.05 U1.21
  SIG w0.127: v1(4.3,8.537) 4.279,8.537 4.077,8.738 3.604,8.738 3.176,9.166 3.176,9.776 3.624,10.224 5.776,10.224 6.938,9.062 7.689,9.062 7.891,9.264 v1(7.9,9.264)
  BOTTOM w0.213: TP1.X 3.025,13.445 3.025,12.355 3.941,11.44 4.841,11.44 5.5,10.78 5.5,9.22 5.01,8.73 4.518,8.73 4.325,8.537 v1(4.3,8.537)
D_P: D1.2 J1.A6 J1.B6 TP2.X U1.22 | length 23.2
  TOP w0.213: v1@4.35,9.214 4.627,9.49 J1.A6 ; J1.B6 7.31,8.69 7.463,8.537 v1(7.9,8.537) 8.169,8.267 8.255,8.267 8.45,8.072 D1.2 ; D1.2@8.45,8.08 9.1,8.73 11.89,8.73 11.99,8.63 13.339,8.63 13.419,8.55 U1.22
  SIG w0.127: v1(4.3,9.264) 4.279,9.264 4.077,9.062 3.738,9.062 3.5,9.3 3.5,9.642 3.758,9.9 5.642,9.9 6.804,8.738 7.689,8.738 7.891,8.537 v1(7.9,8.537)
  BOTTOM w0.213: TP2.X 3.089,11.811 3.8,11.1 4.7,11.1 5.16,10.64 5.16,9.36 4.87,9.07 4.518,9.07 4.325,9.264 v1(4.3,9.264)
GND: ANT1.3 ANT1.4 C1.1 C2.1 C3.2 C4.1 C5.2 C6.1 C7.1 C8.2 C9.2 C10.1 DL2.C J1.A1 J1.A12 J1.B1 J1.B12 JP1.14 JP2.4 PB1.1 PB2.1 Q1.S R3.1 R4.1 R5.1 R6.2 R7.2 R15.2 TP13.X TP14.X U1.23 U1.EXP U2.2 U3.A1 U3.C2 U3.C3 U3.D2 U4.2 U5.7 U5.12 U5.25 U5.29 U5.48 U5.49 U5.50 U5.51 U5.52 | length 66.6
  TOP w0.127: C5.2@14.15,13.1 C5.2@14.296,12.954 ; v1(27.94,11.684) 28.441,11.684 U5.25 30.05,11.65 30.7,11 31.7,11 v1(31.6,10.9) ; U5.51 31.25,10.55 v1(31.6,10.9) ; 32.7,7.4 33.2,7.4 34.45,6.15 U5.48 35.139,5.675 35.6,6.136 v1(35.6,8) v1@35.6,8.1 ; v1(34.3,9.1) 34.35,9.15 U5.7 36.038,9.15 ccw(c36.038,9.662) v1(36.4,9.3) ; v1@34.7,13.7 35,13.4 35,11.725 U5.12@34.959,11.684 ; v1(35.56,11.684) U5.12@34.959,11.684 ; v1@40.75,14.25 v1@40.8,14.2 ; v1(31.6,10.9) 33.6,10.9 34.35,11.65 U5.12 U5.12@34.959,11.684
  TOP w0.15: R5.1 1.877,3.198 2.663,3.198 v1(2.664,3.197) ; v1(12.3,14.2) U3.A1 ; 13,12.311 U3.C2 ; U3.C3 13.697,13.1
  TOP w0.203: J1.A12 J1.B1 ; J1.B12 J1.A1 ; v1(5.9,12.5) v1@6,12.5 ; U4.2 7.6,11.035 C3.2 ; v1(7.663,7.721) 7.663,7.167 8.45,6.38 8.45,6.35 C2.1 ; v1(7.7,10.3) 7.7,10.865 C3.2 ; C4.1 9.565,4.5 U2.2 ; R15.2 9.775,11.775 8.9,10.9 C3.2 ; 10.1,8 v1(10.5,8) ; PB1.1 11.092,10.99 11.7,11.598 v1(11.7,11.6) ; C1.1 15.375,8.075 v1(16.1,8.8) ; 13,12.311 13.053,12.258 13.053,12.047 v1(13.1,12) v1(14.1,12) ; v1(13.227,4.6) 14.265,4.6 C7.1 ; 13.697,13.1 13.843,12.954 14.296,12.954 C5.2 C5.2@14.5,12.4 ; C6.1 15.65,12 v1(14.9,12) ; R7.2 17.322,4.325 ; v1(17.5,3.7) 17.5,4.147 17.322,4.325 ; v1(20.1,3.9) 19.728,4.272 19.653,4.272 R6.2 19.575,4.3 18.37,4.3 Q1.S 17.8,4.803 17.653,4.656 17.322,4.325 ; C10.1 27.606,9.669 27.98,9.669 v1(28.011,9.638) 28.463,9.638 U5.29 ; 31.735,15.293 31.735,16.51 31.749,16.496 31.749,15.135 v1@31.763,15.121 ; 32.7,7.4 32.15,7.95 U5.49 ; C8.2@40.2,14.25 v1@40.75,14.25 ; 41.4,13.5 41.296,13.396 41.296,12.506 41.297,12.505 41.297,12.371 41.468,12.2 41.658,12.2 41.908,12.45 v1@41.95,12.45 ; v1(14.1,12) v1(14.9,12) ; v1(14.1,12) C5.2@14.5,12.4 ; C5.2@14.5,12.4 14.66,12.24 v1(14.9,12) ; U5.49 U5.52 U5.51 U5.50 U5.49
  TOP w0.254: C2.1@8.45,6.35 10.1,8
  TOP w0.356: J1.A12 5.321,5.3 v1(5.9,5.3)
  TOP w0.508: J1.A1 5.301,12.5 v1(5.9,12.5) ; v1(41.9,12.5) 41.95,12.45 42.38,12.02 ANT1.4 ; ANT1.3 42.38,5.739 42.6,5.519 v1(42.6,5.5)
  other v1: 39,2.8 39.9,2.8 40.8,2.8 41.7,2.8 42.6,2.8 9.5,3.2 38.1,3.4 39,3.7 39.9,3.7 40.8,3.7 41.7,3.7 42.6,3.7 38.9,4.4 41.7,4.6 42.6,4.6 38.8,5.1 41.9,5.4 40,5.5 40.9,5.5 0.635,5.842 2.667,5.842 25.42,6.595 18.8,6.8 19.6,6.8 24.9,7.1 39.7,7.2 15.1,7.8 16.1,7.8 3.863,7.921 12.2,8 36.4,8 39.7,8 37.2,8.1 31.7,8.4 38.2,8.7 15.1,8.8 17.1,8.8 31.2,8.9 32.149,8.9 31.7,9.4 37.2,9.5 39.7,9.7 15.1,9.8 16.1,9.8 17.1,9.8 10.541,10.033 38.8,10.046 39.7,10.6 3.3,10.7 38.8,10.946 37.5,11 39.7,11.4 0.635,11.938 38.9,11.946 37.6,12.1 39.9,12.2 42.6,12.5 39.2,12.8 37.7,12.9 40,13 42.6,13.4 38.1,13.6 33.401,13.716 34.671,13.716 41.5,13.8 37,14 38.8,14.1 40.8,14.3 42.6,14.3 39.5,14.35 0.635,14.859 3.175,14.859 6.3,15 31.763,15.021 16.46,15.1 19,15.1 24.063,15.121 26.663,15.121 29.163,15.121 41.8,15.2 42.6,15.2
MGM_AREF: R9.2 SJ1.2 U5.15 | length 10.1
  TOP w0.127: SJ1.2 v1(26.2,13.9) R9.2 ; v1(33.4,12.8) 33.4,12.175 U5.15
  BOTTOM w0.127: v1(26.2,13.9) 32.3,13.9 v1(33.4,12.8)
MGM_RESET_CTL_4: Q1.G R6.1 U1.3 | length 4.9
  TOP w0.127: U1.3 15.85,6.15 16.5,5.5 18.17,5.5 Q1.G 18.805,4.875 R6.1
MISO: JP2.15 U5.23 | length 30.7
  TOP w0.127: v1(20.535,9.99) 21.316,9.99 21.941,10.615 21.941,12.101 22.539,12.699 29.151,12.699 29.45,12.4 U5.23
  SIG w0.127: JP2.15@3.81,16.51 6.02,14.3 9.9,14.3 12.9,11.3 14.2,11.3 15,10.5 20.024,10.5 v1(20.535,9.99)
MOSI: JP2.14 U5.24 | length 29.9
  TOP w0.127: v1(20.124,9.576) v1(20.124,9.576) 20.707,9.574 20.709,9.576 21.442,9.576 22.195,10.328 22.195,11.996 22.644,12.445 28.055,12.445 28.375,12.125 U5.24
  SIG w0.127: JP2.14@6.35,16.51 8.16,14.7 10.1,14.7 12.216,12.584 14.916,12.584 16.5,11 20.3,11 21,10.3 21,9.649 20.926,9.574 v1(20.124,9.576) v1(20.124,9.576)
NetANT1_1: ANT1.1 C9.1 R16.2 | length 2.5
  TOP w0.254: ANT1.1 R16.2@40.78,13.105
NetC5_1: C5.1 Q3.2 U3.A3 U3.B1 U3.C1 U3.D1 U4.6 | length 13.9
  TOP w0.127: Q3.2 11.45,14.35 12.1,13.7 12.1,13.5 ; U3.D1 12.2,12.7 12.1,12.8 12.1,13.1 ; U3.C1 12.1,13.1 ; U3.B1 12.1,13.5 ; 12.1,13.1 12.1,13.5
  TOP w0.15: U3.A3 13.75,14.25
  TOP w0.254: Q3.2 Q3.2@11.45,14.35 ; 13.75,14.25 14.467,14.25 C5.1
  TOP w0.381: U4.6@6.95,14.435 6.95,14.72 7.33,15.1 10.6,15.1 11.091,14.61 11.091,14.51 11.25,14.35 Q3.2 ; Q3.2@11.45,14.35 12.2,15.1 13.9,15.1 14.225,14.775 14.225,14.492 C5.1@14.467,14.25
NetC8_1: C8.1 R16.1 U5.6 | length 9.5
  TOP w0.254: U5.6 36.593,8.65 36.594,8.65 ccw(c36.594,10.256) 38.2,10.256 38.2,12.08 cw(c39.795,12.08) 39.795,13.675 R16.1@40.8,13.675
NetDL1_1: DL1.1 R13.1 | length 2.1
  TOP w0.127: R13.1 22.999,7.52 22.899,7.621 22.899,7.626 22.655,7.87 22.655,8.756 22.844,8.945 23.065,8.945 DL1.1
NetDL1_2: DL1.2 R14.1 | length 1
  TOP w0.127: DL1.2 23.455,8.155 23.455,7.72 23.559,7.616 23.559,7.61 23.649,7.52 R14.1
NetDL1_3: DL1.3 R12.1 | length 0.9
  TOP w0.127: DL1.3 24.145,8.255 24.145,7.964 24.305,7.803 R12.1
NetDL2_A: DL2.A R11.1 | length 0.8
  TOP w0.127: DL2.A@18.4,13.45 DL2.A@18.425,13.425 ; DL2.A 18.525,13.425 R11.1@18.525,12.7
NetJ1_SHIELD4: J1.SHIELD4 R5.2 | length 1.4
  TOP w0.3: R5.2 0.925,4.094 J1.SHIELD4
NetJP1_15: JP1.15 SJ3.1 | length 6.6
  TOP w0.508: SJ3.1 33.905,3.905 34.274,3.536 34.369,3.536 34.94,2.965 36.918,2.965 38.493,1.39 39.235,1.39 JP1.15@39.355,1.27
NetL1_1: L1.1 U3.B3 | length 2.5
  TOP w0.15: U3.B3 13.8,13.5
  TOP w0.254: 13.8,13.5 15.45,13.5 L1.1
NetPB2_2: PB2.2 R9.1 | length 8.3
  TOP w0.127: PB2.2 20.9,11.6 22.253,12.953 25.956,12.953 26.403,13.4 27.268,13.4 27.45,13.582 R9.1
NetQ3_1: Q3.1 R8.2 U4.5 | length 6.4
  TOP w0.127: U4.5 7.6,13.1 v1(7.9,12.8) ; v1(10.4,13) Q3.1@11.3,13
  TOP w0.254: Q3.1@11.3,13 Q3.1 11.575,12.825 R8.2
  SIG w0.127: v1(7.9,12.8) 8.3,12.4 9.8,12.4 v1(10.4,13)
NetR11_2: R11.2 SJ4.2 | length 2.1
  TOP w0.127: R11.2 19.489,12.65 19.569,12.73 19.93,12.73 20.095,12.895 SJ4.2@20.095,13.9
NetU5_35: U5.35 Y1.2 | length 3.1
  TOP w0.127: Y1.2 26.65,8.15 27.3,7.5 27.3,7 27.65,6.65 U5.35
NetU5_36: U5.36 Y1.1 | length 2.4
  TOP w0.127: Y1.1 26.55,5.9 27.6,5.9 27.85,6.15 U5.36
PTI_DATA: JP2.12 U5.32 | length 21.6
  TOP w0.127: U5.32 28.525,8.1 v1(29,8.1)
  SIG w0.127: JP2.12@11.415,16.51 12.848,15.077 14.623,15.077 16.3,13.4 19.3,13.4 22.422,10.278 26.822,10.278 v1(29,8.1)
PTI_SYNC: JP2.13 U5.31 | length 23
  TOP w0.127: v1(27.8,8.5) 27.862,8.562 28.387,8.562 U5.31
  SIG w0.127: JP2.13@8.875,16.51 12.385,13 15.2,13 16.7,11.5 20.5,11.5 22.1,9.9 25.5,9.9 26.9,8.5 v1(27.8,8.5)
R\E\S\E\T\: JP2.3 PB1.2 Q1.D R10.1 TP7.X U5.47 | length 54.1
  TOP w0.127: PB1.2 11.094,6.79 12.098,5.787 12.098,5.467 v1(12.104,5.462) ; v1@12.1,5.484 12.1,3.4 13,2.5 17.07,2.5 Q1.D 18.87,3.73 19.6,3 22.6,3 23.2,2.4 29.127,2.4 31.977,5.25 33.95,5.25 ; U5.47 33.95,5.25 ; R10.1 36.232,5.593 36.232,5.25 ; v1(37.926,4.423) 37.902,4.4 36.411,4.4 36.232,4.579 36.232,5.25 ; 33.95,5.25 36.232,5.25
  SIG w0.127: JP2.3@34.275,16.51 34.275,14.825 35.257,13.843 36.322,13.843 37.084,13.081 37.084,11.916 37.6,11.4 38.9,11.4 39.2,11.1 39.2,9.8 39,9.6 39,7.7 37.6,6.3 37,6.3 36.2,5.5 36.2,4.611 36.411,4.4 37.902,4.4 v1(37.926,4.423)
  BOTTOM w0.127: TP7.X 11.323,6.242 v1(12.104,5.462)
RGB_B: R13.2 U5.40 | length 11.2
  TOP w0.127: R13.2 23.005,6.595 23.88,5.72 23.88,4.187 24.667,3.4 28.555,3.4 30.45,5.295 U5.40
RGB_G: R14.2 U5.39 | length 9.9
  TOP w0.127: R14.2 23.655,6.545 24.3,5.9 24.3,4.3 24.9,3.7 28.355,3.7 29.95,5.295 U5.39
RGB_R: R12.2 U5.38 | length 8.5
  TOP w0.127: R12.2 24.305,6.495 24.7,6.1 24.7,4.5 25.2,4 28.1,4 29.45,5.35 U5.38
SAMD11_N_RESET_4: R2.2 TP10.X U1.18 | length 39.1
  TOP w0.127: v1(12.3,11.2) 12.387,11.2 12.562,11.375 R2.2 14.575,11.375 14.764,11.186 14.764,10.911 U1.18
  SIG w0.127: v1(35.5,14.4) 36.3,14.4 36.9,15 41.1,15 42,14.1 v1(42,13.2)
  BOTTOM w0.127: v1(12.3,11.2) 14,11.2 14.2,11 19.488,11 20.382,11.895 20.382,13.456 21.081,14.154 21.327,14.4 v1(35.5,14.4) ; TP10.X 41.803,11.464 41.3,11.967 41.3,12.9 41.6,13.2 v1(42,13.2)
SAMD11_PA02_4: Q2.S U1.1 | length 2
  TOP w0.127: U1.1 14.85,5.85 15.025,5.675 15.025,5.045 Q2.S
SAMD11_PA05_4: Q5.S U1.4 | length 5.6
  TOP w0.127: U1.4 16.35,6.15 16.7,5.8 20.108,5.8 20.4,5.508 Q5.S
SAMD11_PA08_4: Q4.S U1.7 | length 6.6
  TOP w0.127: U1.7 18.175,7.6 21.8,7.6 22.3,7.1 Q4.S
SAMD11_RX: Q5.D U5.41 | length 12.1
  TOP w0.127: Q5.D 21.47,4.3 23.132,4.3 24.332,3.1 28.8,3.1 30.95,5.25 U5.41
SAMD11_SWCLK_4: TP3.X U1.19 | length 33.2
  TOP w0.127: v1(13.7,10.6) 13.7,10.569 13.52,10.389 13.52,10.2 13.67,10.05 U1.19
  BOTTOM w0.127: v1(13.7,10.6) 19.447,10.6 20.636,11.79 20.636,13.351 21.186,13.9 24.9,13.9 25.913,12.888 25.913,11.713 25.873,11.673 25.873,11.135 26.408,10.6 26.842,10.6 27.418,11.176 28.321,11.176 28.845,11.7 29.6,11.7 30.895,10.405 33.105,10.405 33.35,10.65 33.85,10.65 34.095,10.405 37.395,10.405 38.1,9.7 38.444,9.7 TP3.X
SAMD11_SWDIO_4: R1.1 TP4.X U1.20 | length 44.2
  TOP w0.127: v1(12.3,9.8) 12.387,9.8 12.562,9.625 R1.1 14,9.625 U1.20 ; v1@12.3,9.9 v1@12.35,9.85
  BOTTOM w0.127: v1(12.3,9.8) 12.901,9.199 12.901,7.501 12.3,6.9 12.3,6.4 12.604,6.097 13.196,6.097 13.2,6.1 16.542,6.1 17.663,7.221 24.17,7.221 25.745,8.795 25.745,9.289 26.099,9.643 27.198,9.643 27.755,10.2 28.2,10.2 28.5,9.9 28.5,6.9 29.186,6.214 31.262,6.214 32.948,7.9 35.112,7.9 35.595,7.418 37.506,7.418 38.335,6.588 38.335,5.897 38.651,5.581 39.29,5.581 39.871,5 41.1,5 41.4,5.3 41.4,5.896 41.803,6.299 TP4.X ; v1@12.3,9.9 v1@12.35,9.85
SAMD11_TX: Q4.D U5.42 | length 10.5
  TOP w0.127: Q4.D 23.73,2.8 28.967,2.8 31.45,5.283 U5.42
SWCLK: TP9.X U1.2 U5.16 | length 30.6
  TOP w0.127: U1.2 15.35,5.85 v1(15.7,5.5) ; v1(32.8,11.5) 33.048,11.748 33.048,12.027 U5.16
  SIG w0.127: v1(15.7,5.5) 18,7.8 22.024,7.8 22.724,8.5 25.5,8.5 28.1,5.9 30.6,5.9 33,8.3 33,9.9 32.817,10.083 32.817,11.483 v1(32.8,11.5)
  BOTTOM w0.127: v1(32.8,11.5) 33.499,12.199 35.945,12.199 TP9.X
SWDIO: Q2.D TP8.X U5.17 | length 33
  TOP w0.127: Q2.D v1(15.7,4.3) ; v1(32.1,11.5) 32.45,11.85 U5.17
  SIG w0.127: v1(15.7,4.3) 15.654,4.3 15.1,4.854 15.1,5.75 17.55,8.2 21.2,8.2 21.9,8.9 25.8,8.9 28.4,6.3 30.2,6.3 32.6,8.7 32.6,9.201 32.1,9.701 v1(32.1,11.5)
  BOTTOM w0.127: TP8.X 27.283,12.141 31.459,12.141 v1(32.1,11.5)
UART0_RX: JP2.2 U5.20 | length 8.3
  TOP w0.127: U5.20 30.95,13.25 33,15.3 35.605,15.3 JP2.2@36.815,16.51
UART0_TX: JP2.1 U5.19 | length 10.3
  TOP w0.127: U5.19 31.45,13.15 33.2,14.9 37.745,14.9 JP2.1@39.355,16.51
USB_SHIELD_3: C2.2 D1.1 J1.SHIELD2 | length 5.1
  TOP w0.508: J1.SHIELD2 4.929,4.349 6.069,4.349 6.75,5.03 D1.1
VUSB: C3.1 C4.2 D1.4 J1.A4 J1.A9 J1.B4 J1.B9 Q2.G Q4.G Q5.G R7.1 R8.1 SJ4.1 TP5.X U2.1 U2.3 U4.1 | length 88.8
  TOP w0.127: U2.3 11.292,3.55 11.6,3.858 11.6,5.184 11.334,5.45 U2.1 ; v1@14.3,3.7 v1(14.3,3.6) 14.3,3.1 14.5,2.9 15.9,2.9 16.2,3.2 Q2.G 16.205,4.875 R7.1 ; v1(19.678,12.251) 21.151,12.251 21.705,12.805 SJ4.1@21.705,13.9 ; v1(20.9,5.6) 21.2,5.6 21.4,5.4 Q5.G ; v1(22.8,5.6) 23.1,5.6 23.3,5.4 Q4.G
  TOP w0.254: v1(4.3,6.6) 4.313,6.613 5.274,6.613 J1.A9 J1.B4 ; J1.B9 J1.A4 v1@6.2,11.165 ; v1(6.2,11.2) 6.2,11.15 6.45,10.9 6.751,10.9 C3.1 6.751,10.786 6.751,10.51 6.651,10.41 6.651,9.956 D1.4 ; C3.1@6.838,10.927 6.95,11.04 U4.1 ; v1(10.4,12.2) R8.1
  TOP w0.508: v1(9.5,6.1) C4.2 10.685,5.435 U2.1
  SIG w0.254: 5.9,11.5 6.3,11.9 10.1,11.9 v1(10.4,12.2)
  SIG w0.508: v1(4.3,6.6) 3.1,6.6 1.9,7.8 1.9,10.6 2.8,11.5 5.9,11.5 v1(6.2,11.2) 8.9,11.2 9.5,10.6 v1(9.5,6.1)
  BOTTOM w0.127: v1@6.2,11.211 6.2,11.7 6.4,11.9 6.4,13.3 7.6,14.5 11.8,14.5 12.2,14.9 13.3,14.9 14.6,13.6 17.5,13.6 18.849,12.251 v1(19.678,12.251)
  BOTTOM w0.508: v1(9.5,6.1) 9.5,5.7 11.6,3.6 v1(14.3,3.6) 16.242,3.6 18.242,5.6 v1(20.9,5.6) v1(22.8,5.6) 24.726,3.674 29.103,3.674 30.47,5.041 TP5.X
pads on no net: ANT1.2 Fiducial_1.1 Fiducial_2.1 J1.A8 J1.B8 J1.FIXING J1.SHIELD1 J1.SHIELD3 JP1.13 U1.5 U1.6 U1.8 U1.9 U1.10 U1.11 U1.12 U1.13 U1.14 U1.15 U1.16 U1.17 U2.4 U3.D3 U4.4 U5.1 U5.2 U5.3 U5.4 U5.5 U5.26 U5.27

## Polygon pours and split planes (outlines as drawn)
GND on TOP "GND_L01_P004" (solid, remove dead copper, pour order 4): 0,17.78 43.18,17.78 43.18,0 0,0
+3V3 on TOP "NONET_L04_P-001" (solid, remove dead copper, pour order 0): 28.728,10.373 28.728,9.002 28.606,8.881 24.221,8.881 22.778,7.438 18.55,7.438 17.62,8.881 17.62,12.247 28.728,12.247
GND on GND "GND_L02_P001" (solid, remove dead copper, pour order 1): 0,17.78 43.18,17.78 43.18,0 0,0
GND on SIG "GND_L03_P002" (solid, remove dead copper, pour order 2): 0,17.78 43.18,17.78 43.18,0 0,0
GND on BOTTOM "GND_L04_P003" (solid, remove dead copper, pour order 3): 0,17.78 43.18,17.78 43.18,0 0,0

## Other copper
TOP:
  pour cut-out: 35.1,3.8 36.825,3.8 39.355,1.27 34.275,1.27 34.275,2.975
  pour cut-out: 39.98,5.76 43.18,5.76 43.18,12.02 39.98,12.02
  pour cut-out: 27.8,8.7 27.36,9.14 24.05,9.14 24.05,6.15 24.7,5.5 27.2,5.5 27.8,6.1
  pour cut-out: 0,17.78 0,16.955 1.27,15.685 41.91,15.685 43.18,16.955 43.18,17.78
  pour cut-out: 0,0 0,0.826 1.27,2.096 41.91,2.096 43.18,0.826 43.18,0
  pour cut-out: 15.4,15.748 18.034,15.748 18.034,12.9 15.4,12.9
GND:
  pour cut-out: 39.98,5.76 43.18,5.76 43.18,12.02 39.98,12.02
SIG:
  pour cut-out: 21.59,17.78 33.005,17.78 34.275,16.51 34.275,10.018 30.857,6.6 28.579,6.6 21.541,13.638
  pour cut-out: 22.656,7.7 25,7.7 26.2,6.5 26.2,5.7 25.7,5.2 22.156,5.2 21.156,6.2
  pour cut-out: 3.81,16.51 3.81,13.59 5.4,12 12.2,12 13,11.2 20.471,11.2 21.575,12.304 21.575,16.51
  pour cut-out: 34.275,16.51 41.91,16.51 41.91,15.71 41,14.8 35.985,14.8
  pour cut-out: 21.575,1.27 21.575,8.025 20.9,8.7 18.845,8.7 11.415,1.27
BOTTOM:
  pour cut-out: 17.9,10.6 17.9,7.955 18.28,7.575 23.417,7.575 25.863,10.021 25.284,10.6
  pour cut-out: 23.5,12.8 23.5,12 22.6,11.1 20.9,12.8
  pour cut-out: 16.6,13.5 18,12.1 17.4,11.5 12.85,11.5 10.951,13.399 11.052,13.5
  pour cut-out: 0,0 0,0.826 1.27,2.096 41.91,2.096 43.18,0.826 43.18,0
  pour cut-out: 0,17.78 0,16.955 1.27,15.685 41.91,15.685 43.18,16.955 43.18,17.78
  text ".Version" at 0.55,7.25 h0.8 r270

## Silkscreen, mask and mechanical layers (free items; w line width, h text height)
Top Overlay:
  drawing of 107 lines, arcs and shapes, not listed
Bottom Overlay:
  drawing of 178 lines, arcs and shapes, not listed
Route Tool Path:
  lines w2: -1,1 -1,0 ccw(c0,0) 0,-1 43.18,-1 ccw(c43.18,0) 44.18,0 44.18,6.5 ; -1,5 -1,13 ; -1,17 -1,17.78 cw(c0,17.78) 0,18.78 43.18,18.78 cw(c43.18,17.78) 44.18,17.78 44.18,10.5
Board:
  the board outline again, w0.1
NANO TP AND SIGNALS:
  drawing of 309 lines, arcs and shapes, not listed
  text "D12" at 3.435,15.14 h0.3
  text "D11" at 6.025,15.14 h0.3
  text "D10" at 8.515,15.14 h0.3
  text "D9" at 11.18,15.14 h0.3
  text "D9" at 11.18,15.14 h0.3
  text "D8" at 13.72,15.14 h0.3
  text "D7" at 16.26,15.14 h0.3
  text "D6" at 18.8,15.14 h0.3
  text "D5" at 21.325,15.14 h0.3
  text "D4" at 23.865,15.14 h0.3
  text "D3" at 26.42,15.14 h0.3
  text "D2" at 28.96,15.14 h0.3
  text "GND" at 31.35,15.14 h0.3
  text "NRST" at 33.74,15.14 h0.3
  text "D1" at 36.63,15.14 h0.3
  text "D0" at 39.12,15.14 h0.3
  text "RX" at 36.58,14.54 h0.3
  text "TX" at 39.12,14.54 h0.3
  text "USB DN" at 2.5,14.11 h0.3
  text "USB DP" at 2.5,11.261 h0.3
  text "GND" at 38.8,10.35 h0.3
  text "RESET" at 41.1,10.35 h0.3
  text "SWCLK" at 38.35,7.85 h0.3
  text "NC" at 41.55,7.85 h0.3
  text "VUSB" at 31.245,5.791 h0.3
  text "3V3" at 38.75,5.25 h0.3
  text "SWDIO" at 41.125,5.25 h0.3
  text "D13" at 3.435,3.02 h0.3
  text "VREF OR" at 7.89,3.02 h0.3
  text "VBUS" at 31.2,3.02 h0.3
  text "NRST OR" at 33.29,3.02 h0.3
  text "SCK" at 3.41,2.42 h0.3
  text "OTHER" at 8.19,2.42 h0.3
  text "5V" at 31.5,2.42 h0.3
  text "OTHER" at 33.59,2.42 h0.3
  text "3V3" at 5.95,2.32 h0.3
  text "A0" at 11.18,2.32 h0.3
  text "A0" at 11.18,2.32 h0.3
  text "A1" at 13.77,2.32 h0.3
  text "A2" at 16.26,2.32 h0.3
  text "A3" at 18.8,2.32 h0.3
  text "A6" at 26.42,2.32 h0.3
  text "A7" at 28.96,2.32 h0.3
  text "GND" at 36.43,2.32 h0.3
  text "VIN" at 38.995,2.32 h0.3
  text "A4" at 21.325,2.311 h0.3
  text "A5" at 23.865,2.311 h0.3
